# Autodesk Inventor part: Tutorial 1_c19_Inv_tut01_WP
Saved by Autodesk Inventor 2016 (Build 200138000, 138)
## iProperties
Created: 2015-04
Part Number: Tutorial 1_c19_Inv_tut01_WP
Material: Generic
Document SubType Name: Modeling
Designer: Sandeep
Density: 1 g/cm^3
Appearance: Default
Author: Sandeep
d0: -157.500 mm
d1: 312.500 mm
d2: 312.500 mm
d3: 280.000 mm
d4: 280.000 mm
d5: 315.000 mm
d6: 0.00 deg
Xmin: -312.500 mm
Ymin: -280.000 mm
Zmin: -157.500 mm
Xmax: 312.500 mm
Ymax: 280.000 mm
Zmax: 157.500 mm
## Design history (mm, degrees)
sketch "Sketch1"
  geometry: L1 (-312.5, 279.93)-(312.5, 279.93); L2 (312.5, 279.93)-(312.5, -280.07); L3 (312.5, -280.07)-(-312.5, -280.07); L4 (-312.5, -280.07)-(-312.5, 279.93); 1 further point
  constraints: 8 end point, 2 parallel, 1 horizontal, 1 perpendicular, 1 other
  dimensions: "d1" = 312.5 distance from line of L4 point (0, -0.07) (= -Xmin); "d2" = 312.5 distance from line of L2 point (0, -0.07) (= Xmax); "d3" = 280 distance from line of L3 point (0, -0.07) (= -Ymin); "d4" = 280 distance from line of L1 point (0, -0.07) (= Ymax)
extrude "Extrusion1" join sketch "Sketch1" distance "d5" = 315 (= Zmax - Zmin); taper "d6" = 0 deg
body "Solid1"
other parameters: "Xmin" = -312.5 [user parameter; used in 1 equation term], "Ymin" = -280 [user parameter; used in 1 equation term], "Zmin" = -157.5 [user parameter; used in 1 equation term], "Xmax" = 312.5 [user parameter; used in 1 equation term], "Ymax" = 280 [user parameter; used in 1 equation term], "Zmax" = 157.5 [user parameter; used in 1 equation term], "d0" = -157.5
